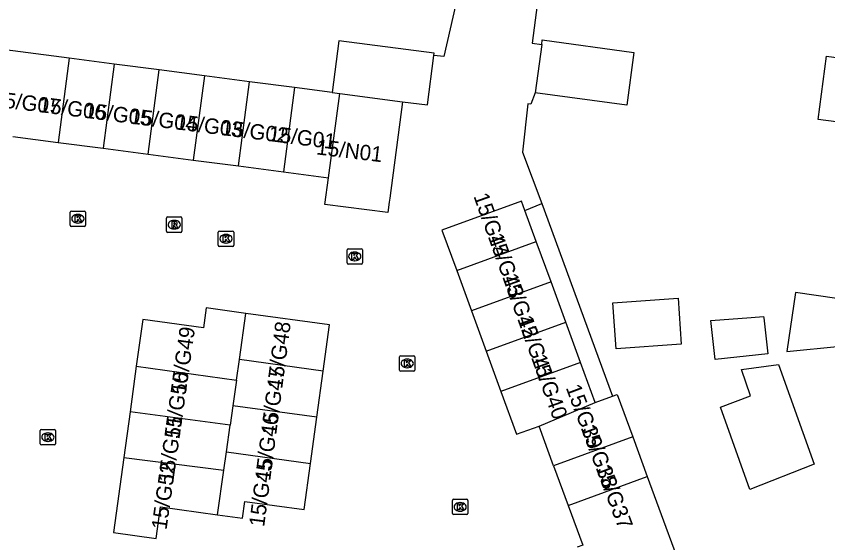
# Model space of a CAD drawing. Extents: x 161258 to 161838, y 380836 to 381727.
# Drawn here: x 161617.4 to 161670.2, y 381523.6 to 381557.9 of the extents above; entities that cross this region are included whole.
import ezdxf

# ---------------------------------------------------------------- set-up
doc = ezdxf.new("R2010")
doc.units = 0
for name, color, linetype in [('IMGEO_Kolk', 7, 'Continuous'), ('IMGEO_Pand', 7, 'Continuous'), ('IMGEO_Pand_nummerreeks', 7, 'Continuous'), ('IMGEO_Rijbaan_lokaal_open', 7, 'Continuous'), ('IMGEO_Rioolput', 7, 'Continuous'), ('IMGEO_Voetpad_open', 7, 'Continuous')]:
    doc.layers.add(name, color=color, linetype=linetype)

msp = doc.modelspace()

# ---------------------------------------------------------------- linework, layer by layer
at = {"layer": 'IMGEO_Kolk'}
for p, q in [((161620.933, 381544.306), (161620.933, 381545.158)), ((161621.008, 381545.232), (161621.86, 381545.232)), ((161621.934, 381545.158), (161621.934, 381544.306)), ((161621.421, 381545.012), (161621.446, 381545.012)), ((161621.86, 381544.232), (161621.008, 381544.232)), ((161621.444, 381544.452), (161621.419, 381544.452)), ((161630.572, 381543.003), (161630.572, 381543.855)), ((161630.647, 381543.929), (161631.499, 381543.929)), ((161631.06, 381543.709), (161631.085, 381543.709)), ((161631.573, 381543.855), (161631.573, 381543.003)), ((161631.083, 381543.149), (161631.058, 381543.149)), ((161631.499, 381542.929), (161630.647, 381542.929)), ((161638.955, 381541.854), (161638.955, 381542.706)), ((161639.03, 381542.78), (161639.882, 381542.78)), ((161639.443, 381542.56), (161639.468, 381542.56)), ((161639.956, 381542.706), (161639.956, 381541.854)), ((161639.466, 381542), (161639.441, 381542)), ((161639.882, 381541.78), (161639.03, 381541.78)), ((161642.371, 381534.881), (161642.371, 381535.733)), ((161642.446, 381535.807), (161643.298, 381535.807)), ((161643.372, 381535.733), (161643.372, 381534.881)), ((161642.859, 381535.587), (161642.884, 381535.587)), ((161643.298, 381534.807), (161642.446, 381534.807)), ((161642.882, 381535.027), (161642.857, 381535.027)), ((161618.978, 381530.082), (161618.978, 381530.934)), ((161619.053, 381531.008), (161619.905, 381531.008)), ((161619.979, 381530.934), (161619.979, 381530.082)), ((161619.466, 381530.788), (161619.491, 381530.788)), ((161619.905, 381530.008), (161619.053, 381530.008)), ((161619.489, 381530.228), (161619.464, 381530.228)), ((161645.817, 381525.542), (161645.817, 381526.394)), ((161645.892, 381526.468), (161646.744, 381526.468)), ((161646.305, 381526.248), (161646.33, 381526.248)), ((161646.818, 381526.394), (161646.818, 381525.542)), ((161646.328, 381525.688), (161646.303, 381525.688)), ((161646.744, 381525.468), (161645.892, 381525.468))]:
    msp.add_line(p, q, dxfattribs=at)
for points in [[(161620.933, 381544.306), (161620.933, 381545.158)], [(161621.008, 381545.232), (161621.86, 381545.232)], [(161621.934, 381545.158), (161621.934, 381544.306)], [(161621.254, 381544.932), (161621.377, 381544.932), (161621.377, 381544.781), (161621.507, 381544.932), (161621.671, 381544.932), (161621.525, 381544.781), (161621.678, 381544.532), (161621.526, 381544.532), (161621.441, 381544.696), (161621.377, 381544.629), (161621.377, 381544.532), (161621.254, 381544.532), (161621.254, 381544.932)], [(161621.86, 381544.232), (161621.008, 381544.232)], [(161630.572, 381543.003), (161630.572, 381543.855)], [(161630.647, 381543.929), (161631.499, 381543.929)], [(161630.893, 381543.629), (161631.016, 381543.629), (161631.016, 381543.478), (161631.146, 381543.629), (161631.31, 381543.629), (161631.164, 381543.478), (161631.317, 381543.229), (161631.165, 381543.229), (161631.08, 381543.393), (161631.016, 381543.326), (161631.016, 381543.229), (161630.893, 381543.229), (161630.893, 381543.629)], [(161631.573, 381543.855), (161631.573, 381543.003)], [(161631.499, 381542.929), (161630.647, 381542.929)], [(161638.955, 381541.854), (161638.955, 381542.706)], [(161639.03, 381542.78), (161639.882, 381542.78)], [(161639.956, 381542.706), (161639.956, 381541.854)], [(161639.276, 381542.48), (161639.399, 381542.48), (161639.399, 381542.329), (161639.529, 381542.48), (161639.693, 381542.48), (161639.547, 381542.329), (161639.7, 381542.08), (161639.548, 381542.08), (161639.463, 381542.244), (161639.399, 381542.177), (161639.399, 381542.08), (161639.276, 381542.08), (161639.276, 381542.48)], [(161639.882, 381541.78), (161639.03, 381541.78)], [(161642.371, 381534.881), (161642.371, 381535.733)], [(161642.446, 381535.807), (161643.298, 381535.807)], [(161643.372, 381535.733), (161643.372, 381534.881)], [(161642.692, 381535.507), (161642.815, 381535.507), (161642.815, 381535.356), (161642.945, 381535.507), (161643.109, 381535.507), (161642.963, 381535.356), (161643.116, 381535.107), (161642.964, 381535.107), (161642.879, 381535.271), (161642.815, 381535.204), (161642.815, 381535.107), (161642.692, 381535.107), (161642.692, 381535.507)], [(161643.298, 381534.807), (161642.446, 381534.807)], [(161618.978, 381530.082), (161618.978, 381530.934)], [(161619.053, 381531.008), (161619.905, 381531.008)], [(161619.979, 381530.934), (161619.979, 381530.082)], [(161619.299, 381530.708), (161619.422, 381530.708), (161619.422, 381530.557), (161619.552, 381530.708), (161619.716, 381530.708), (161619.57, 381530.557), (161619.723, 381530.308), (161619.571, 381530.308), (161619.486, 381530.472), (161619.422, 381530.405), (161619.422, 381530.308), (161619.299, 381530.308), (161619.299, 381530.708)], [(161619.905, 381530.008), (161619.053, 381530.008)], [(161645.817, 381525.542), (161645.817, 381526.394)], [(161645.892, 381526.468), (161646.744, 381526.468)], [(161646.138, 381526.168), (161646.261, 381526.168), (161646.261, 381526.017), (161646.391, 381526.168), (161646.555, 381526.168), (161646.409, 381526.017), (161646.562, 381525.768), (161646.41, 381525.768), (161646.325, 381525.932), (161646.261, 381525.865), (161646.261, 381525.768), (161646.138, 381525.768), (161646.138, 381526.168)], [(161646.818, 381526.394), (161646.818, 381525.542)], [(161646.744, 381525.468), (161645.892, 381525.468)]]:
    msp.add_lwpolyline(points, dxfattribs=at)
for centre, start, end in [((161621.01, 381545.156), 91.552, 178.448), ((161621.01, 381545.156), 91.552, 178.448), ((161621.858, 381545.156), 1.552, 88.448), ((161621.858, 381545.156), 1.552, 88.448), ((161621.01, 381544.308), 181.552, 268.448), ((161621.01, 381544.308), 181.552, 268.448), ((161621.858, 381544.308), 271.552, 358.448), ((161621.858, 381544.308), 271.552, 358.448), ((161630.649, 381543.853), 91.552, 178.448), ((161630.649, 381543.853), 91.552, 178.448), ((161631.497, 381543.853), 1.552, 88.448), ((161631.497, 381543.853), 1.552, 88.448), ((161630.649, 381543.005), 181.552, 268.448), ((161630.649, 381543.005), 181.552, 268.448), ((161631.497, 381543.005), 271.552, 358.448), ((161631.497, 381543.005), 271.552, 358.448), ((161639.032, 381542.704), 91.552, 178.448), ((161639.032, 381542.704), 91.552, 178.448), ((161639.88, 381542.704), 1.552, 88.448), ((161639.88, 381542.704), 1.552, 88.448), ((161639.032, 381541.856), 181.552, 268.448), ((161639.032, 381541.856), 181.552, 268.448), ((161639.88, 381541.856), 271.552, 358.448), ((161639.88, 381541.856), 271.552, 358.448), ((161642.448, 381535.731), 91.552, 178.448), ((161642.448, 381535.731), 91.552, 178.448), ((161643.296, 381535.731), 1.552, 88.448), ((161643.296, 381535.731), 1.552, 88.448), ((161642.448, 381534.883), 181.552, 268.448), ((161642.448, 381534.883), 181.552, 268.448), ((161643.296, 381534.883), 271.552, 358.448), ((161643.296, 381534.883), 271.552, 358.448), ((161619.055, 381530.932), 91.552, 178.448), ((161619.055, 381530.932), 91.552, 178.448), ((161619.903, 381530.932), 1.552, 88.448), ((161619.903, 381530.932), 1.552, 88.448), ((161619.055, 381530.084), 181.552, 268.448), ((161619.055, 381530.084), 181.552, 268.448), ((161619.903, 381530.084), 271.552, 358.448), ((161619.903, 381530.084), 271.552, 358.448), ((161645.894, 381526.392), 91.552, 178.448), ((161645.894, 381526.392), 91.552, 178.448), ((161646.742, 381526.392), 1.552, 88.448), ((161646.742, 381526.392), 1.552, 88.448), ((161645.894, 381525.544), 181.552, 268.448), ((161645.894, 381525.544), 181.552, 268.448), ((161646.742, 381525.544), 271.552, 358.448), ((161646.742, 381525.544), 271.552, 358.448)]:
    msp.add_arc(centre, 0.0765, start, end, dxfattribs=at)
for centre, major_axis, ratio, start_param, end_param in [((161621.42, 381544.732), (-0.387, 0.002), 0.722429, 4.712389, 7.853982), ((161621.445, 381544.732), (-0.39, 0.002), 0.717154, 1.570796, 4.712389), ((161631.059, 381543.429), (-0.387, 0.002), 0.722429, 4.712389, 7.853982), ((161631.084, 381543.429), (-0.39, 0.002), 0.717154, 1.570796, 4.712389), ((161639.442, 381542.28), (-0.387, 0.002), 0.722429, 4.712389, 7.853982), ((161639.467, 381542.28), (-0.39, 0.002), 0.717154, 1.570796, 4.712389), ((161642.858, 381535.307), (-0.387, 0.002), 0.722429, 4.712389, 7.853982), ((161642.883, 381535.307), (-0.39, 0.002), 0.717154, 1.570796, 4.712389), ((161619.465, 381530.508), (-0.387, 0.002), 0.722429, 4.712389, 7.853982), ((161619.49, 381530.508), (-0.39, 0.002), 0.717154, 1.570796, 4.712389), ((161646.304, 381525.968), (-0.387, 0.002), 0.722429, 4.712389, 7.853982), ((161646.329, 381525.968), (-0.39, 0.002), 0.717154, 1.570796, 4.712389)]:
    msp.add_ellipse(centre, major_axis=major_axis, ratio=ratio, start_param=start_param, end_param=end_param, dxfattribs=at)
at = {"layer": 'IMGEO_Pand'}
for points in [[(161620.857, 381555.19), (161612.34, 381556.304)], [(161644.605, 381555.362), (161644.624, 381555.509), (161638.417, 381556.322), (161637.975, 381552.951)], [(161651.628, 381556.084), (161651.667, 381556.374), (161657.632, 381555.562), (161657.163, 381552.122), (161651.199, 381552.935)], [(161651.628, 381556.084), (161651.199, 381552.935)], [(161620.857, 381555.19), (161620.14, 381549.701)], [(161623.793, 381554.806), (161620.857, 381555.19)], [(161642.556, 381552.352), (161644.182, 381552.138), (161644.605, 381555.362)], [(161672.15, 381550.861), (161669.619, 381551.2), (161670.169, 381555.312), (161672.7, 381554.974), (161672.15, 381550.861)], [(161623.793, 381554.806), (161623.075, 381549.318)], [(161626.728, 381554.422), (161623.793, 381554.806)], [(161626.01, 381548.934), (161626.728, 381554.422)], [(161629.663, 381554.038), (161626.728, 381554.422)], [(161629.663, 381554.038), (161628.946, 381548.551)], [(161632.598, 381553.654), (161629.663, 381554.038)], [(161631.881, 381548.167), (161632.598, 381553.654)], [(161635.533, 381553.271), (161632.598, 381553.654)], [(161635.533, 381553.271), (161634.816, 381547.784)], [(161637.975, 381552.951), (161635.533, 381553.271)], [(161637.751, 381547.4), (161638.494, 381552.883)], [(161637.975, 381552.951), (161638.494, 381552.883)], [(161638.494, 381552.883), (161642.556, 381552.352)], [(161642.556, 381552.352), (161641.735, 381546.072), (161641.7, 381545.808), (161641.611, 381545.134), (161637.516, 381545.668), (161637.751, 381547.4)], [(161617.205, 381550.085), (161620.14, 381549.701)], [(161620.14, 381549.701), (161623.075, 381549.318)], [(161623.075, 381549.318), (161626.01, 381548.934)], [(161626.01, 381548.934), (161628.946, 381548.551)], [(161628.946, 381548.551), (161631.881, 381548.167)], [(161631.881, 381548.167), (161634.816, 381547.784)], [(161634.816, 381547.784), (161637.751, 381547.4)], [(161650.533, 381545.273), (161650.311, 381545.878), (161645.132, 381543.981), (161646.093, 381541.357)], [(161651.272, 381543.254), (161650.533, 381545.273)], [(161646.093, 381541.357), (161651.272, 381543.254)], [(161652.233, 381540.629), (161651.272, 381543.254)], [(161646.093, 381541.357), (161647.054, 381538.732)], [(161652.233, 381540.629), (161647.054, 381538.732)], [(161653.195, 381538.005), (161652.233, 381540.629)], [(161668.145, 381539.932), (161667.583, 381536.076), (161674.562, 381536.774), (161674.879, 381538.951), (161668.145, 381539.932)], [(161656.469, 381536.263), (161656.256, 381539.255), (161660.501, 381539.557), (161660.713, 381536.564), (161656.469, 381536.263)], [(161632.368, 381538.566), (161629.776, 381538.922), (161629.598, 381537.635), (161625.651, 381538.177), (161625.233, 381535.14)], [(161631.944, 381535.561), (161632.368, 381538.566)], [(161637.397, 381534.812), (161637.81, 381537.817), (161632.368, 381538.566)], [(161647.054, 381538.732), (161648.015, 381536.108)], [(161666.337, 381535.926), (161662.922, 381535.559), (161662.647, 381538.095), (161665.273, 381538.297), (161666.073, 381538.359), (161666.082, 381538.274), (161666.337, 381535.926)], [(161648.015, 381536.108), (161653.195, 381538.005)], [(161654.156, 381535.38), (161653.195, 381538.005)], [(161648.015, 381536.108), (161648.976, 381533.483)], [(161625.233, 381535.14), (161624.824, 381532.161)], [(161625.233, 381535.14), (161631.755, 381534.222)], [(161631.755, 381534.222), (161631.944, 381535.561)], [(161637.397, 381534.812), (161631.944, 381535.561)], [(161654.156, 381535.38), (161648.976, 381533.483)], [(161655.117, 381532.756), (161654.156, 381535.38)], [(161669.359, 381528.753), (161665.18, 381527.11), (161663.259, 381532.456), (161665.21, 381533.199), (161664.632, 381534.923), (161667.033, 381535.244), (161669.359, 381528.753)], [(161636.984, 381531.806), (161637.397, 381534.812)], [(161631.755, 381534.222), (161631.52, 381532.557)], [(161648.976, 381533.483), (161649.996, 381530.699), (161651.452, 381531.232)], [(161655.117, 381532.756), (161656.242, 381533.168)], [(161656.242, 381533.168), (161656.549, 381533.281), (161657.555, 381530.535)], [(161631.52, 381532.557), (161631.34, 381531.283)], [(161636.984, 381531.806), (161631.52, 381532.557)], [(161651.452, 381531.232), (161655.117, 381532.756)], [(161624.824, 381532.161), (161624.414, 381529.178)], [(161631.34, 381531.283), (161624.824, 381532.161)], [(161636.57, 381528.8), (161636.984, 381531.806)], [(161631.096, 381529.553), (161631.34, 381531.283)], [(161652.399, 381528.646), (161651.452, 381531.232)], [(161657.555, 381530.535), (161652.399, 381528.646)], [(161657.555, 381530.535), (161658.502, 381527.949)], [(161630.928, 381528.364), (161631.096, 381529.553)], [(161631.096, 381529.553), (161636.57, 381528.8)], [(161624.414, 381529.178), (161623.743, 381524.3), (161626.518, 381523.919), (161626.8, 381525.972), (161630.518, 381525.46)], [(161624.414, 381529.178), (161630.928, 381528.364)], [(161630.518, 381525.46), (161632.15, 381525.236), (161632.299, 381526.326), (161636.157, 381525.795), (161636.57, 381528.8)], [(161630.518, 381525.46), (161630.928, 381528.364)], [(161652.399, 381528.646), (161653.346, 381526.061)], [(161653.346, 381526.061), (161658.502, 381527.949)], [(161658.502, 381527.949), (161661.283, 381520.357)], [(161653.346, 381526.061), (161654.293, 381523.475), (161653.937, 381523.345)]]:
    msp.add_lwpolyline(points, dxfattribs=at)
at = {"layer": 'IMGEO_Rijbaan_lokaal_open'}
for points in [[(161648.68, 381581.562), (161649.218, 381580.79), (161648.988, 381578.933), (161646.845, 381562.231), (161645.253, 381555.29), (161644.605, 381555.362)], [(161654.227, 381580.806), (161650.995, 381556.159), (161651.628, 381556.084)], [(161651.199, 381552.935), (161650.911, 381552.193), (161650.724, 381552.207), (161650.382, 381549.056), (161651.64, 381545.721)], [(161650.533, 381545.273), (161651.64, 381545.721)]]:
    msp.add_lwpolyline(points, dxfattribs=at)
at = {"layer": 'IMGEO_Rioolput'}
for p, q in [((161627.206, 381543.919), (161627.206, 381544.771)), ((161627.281, 381544.845), (161628.133, 381544.845)), ((161627.694, 381544.625), (161627.719, 381544.625)), ((161628.207, 381544.771), (161628.207, 381543.919)), ((161628.133, 381543.845), (161627.281, 381543.845)), ((161627.717, 381544.065), (161627.692, 381544.065))]:
    msp.add_line(p, q, dxfattribs=at)
for points in [[(161627.206, 381543.919), (161627.206, 381544.771)], [(161627.281, 381544.845), (161628.133, 381544.845)], [(161628.207, 381544.771), (161628.207, 381543.919)], [(161627.795, 381544.543), (161627.543, 381544.545), (161627.543, 381544.145)], [(161627.543, 381544.145), (161627.667, 381544.145), (161627.667, 381544.307), (161627.678, 381544.307)], [(161627.721, 381544.464), (161627.667, 381544.464), (161627.667, 381544.383)], [(161627.667, 381544.383), (161627.719, 381544.383)], [(161627.725, 381544.278), (161627.796, 381544.145), (161627.936, 381544.145), (161627.871, 381544.271)], [(161628.133, 381543.845), (161627.281, 381543.845)]]:
    msp.add_lwpolyline(points, dxfattribs=at)
for centre, radius, start, end in [((161627.283, 381544.769), 0.0765, 91.552, 178.448), ((161627.283, 381544.769), 0.0765, 91.552, 178.448), ((161628.131, 381544.769), 0.0765, 1.552, 88.448), ((161628.131, 381544.769), 0.0765, 1.552, 88.448), ((161627.677, 381544.254), 0.0533, 26.0293, 88.6989), ((161627.703, 381544.572), 0.19, 274.7715, 282.9687), ((161627.727, 381544.368), 0.0964, 77.0061, 93.1865), ((161627.741, 381544.425), 0.0378, 276.6634, 79.6772), ((161627.794, 381544.433), 0.109, 350.3612, 89.416), ((161627.792, 381544.433), 0.112, 277.5842, 350.9817), ((161627.776, 381544.218), 0.108, 29.5134, 73.7905), ((161627.283, 381543.921), 0.0765, 181.552, 268.448), ((161627.283, 381543.921), 0.0765, 181.552, 268.448), ((161628.131, 381543.921), 0.0765, 271.552, 358.448), ((161628.131, 381543.921), 0.0765, 271.552, 358.448)]:
    msp.add_arc(centre, radius, start, end, dxfattribs=at)
for centre, major_axis, ratio, start_param, end_param in [((161627.693, 381544.345), (-0.387, 0.002), 0.722429, 4.712389, 7.853982), ((161627.718, 381544.345), (-0.39, 0.002), 0.717154, 1.570796, 4.712389)]:
    msp.add_ellipse(centre, major_axis=major_axis, ratio=ratio, start_param=start_param, end_param=end_param, dxfattribs=at)
at = {"layer": 'IMGEO_Voetpad_open'}
msp.add_lwpolyline([(161651.64, 381545.721), (161656.242, 381533.168)], dxfattribs=at)

# ---------------------------------------------------------------- texts
at = {"layer": 'IMGEO_Pand_nummerreeks'}
for s, rotation, p in [('15/G07', 352.8008, (161615.872, 381552.062)), ('15/G06', 352.8008, (161618.841, 381551.687)), ('15/G05', 352.8008, (161621.81, 381551.312)), ('15/G04', 352.8008, (161624.778, 381550.937)), ('15/G03', 352.8008, (161627.747, 381550.562)), ('15/G02', 352.8008, (161630.71, 381550.188)), ('15/G01', 352.8008, (161633.794, 381549.799)), ('15/N01', 353.1646, (161636.919, 381548.925)), ('15/G44', 289.6538, (161647.172, 381546.207)), ('15/G43', 289.6538, (161648.109, 381543.582)), ('15/G42', 289.6538, (161649.045, 381540.963)), ('15/G41', 289.6538, (161650.022, 381538.228)), ('15/G48', 82.5686, (161634.728, 381533.622)), ('15/G49', 81.9409, (161628.451, 381533.276)), ('15/G40', 289.6538, (161650.923, 381535.704)), ('15/G50', 81.9409, (161628.035, 381530.34)), ('15/G47', 82.5686, (161634.337, 381530.624)), ('15/G39', 290.4716, (161653.18, 381533.739)), ('15/G46', 82.5686, (161633.946, 381527.629)), ('15/G51', 81.9409, (161627.633, 381527.503)), ('15/G38', 290.4723, (161654.154, 381531.13)), ('15/G52', 81.9409, (161627.2, 381524.445)), ('15/G45', 82.5686, (161633.556, 381524.634)), ('15/G37', 290.4723, (161655.125, 381528.529))]:
    msp.add_text(s, height=1, rotation=rotation, dxfattribs=at).set_placement(p)

doc.saveas('drawing.dxf')
